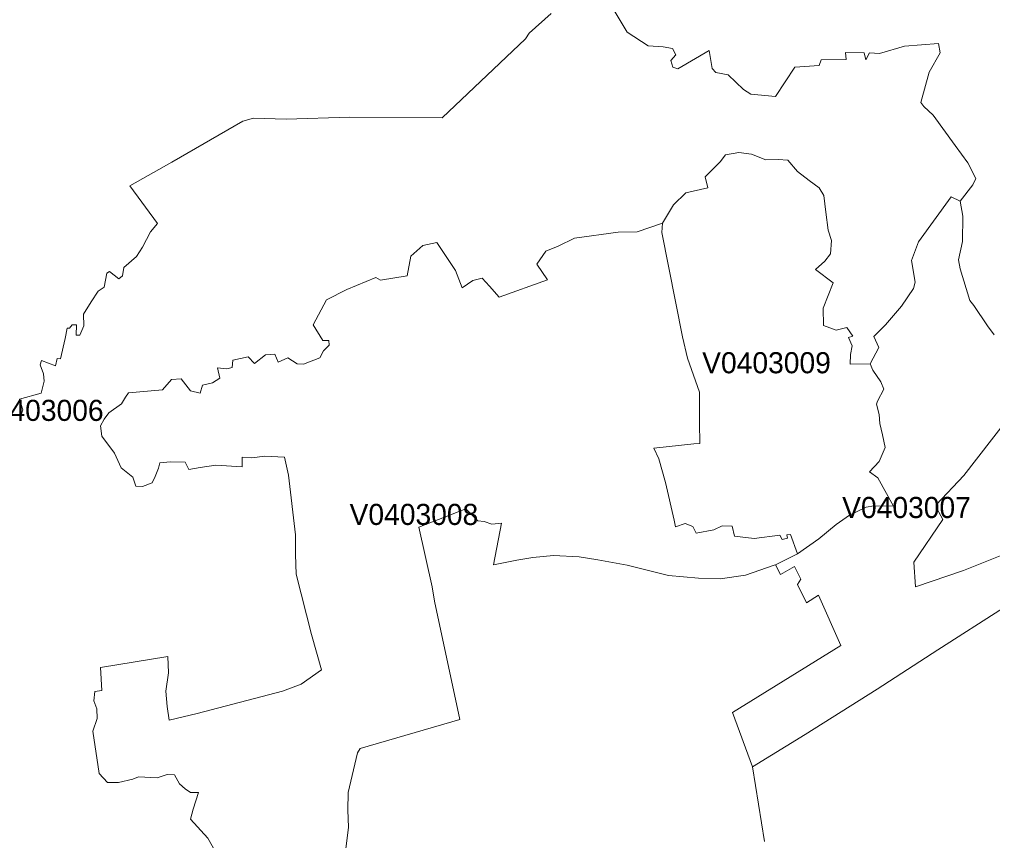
# Model space of a CAD drawing. Extents: x 369010 to 735936, y 6377141 to 6616555.
# Drawn here: x 425415 to 430026, y 6480546 to 6484437 of the extents above; entities that cross this region are included whole.
import ezdxf
from ezdxf.enums import TextEntityAlignment as Align

# ---------------------------------------------------------------- set-up
doc = ezdxf.new("R2010")
doc.units = 0
doc.header["$LTSCALE"] = 40
doc.layers.add('3', color=7, linetype='Continuous', lineweight=13)
doc.layers.add('4', color=7, linetype='Continuous')

msp = doc.modelspace()

# ---------------------------------------------------------------- linework, layer by layer
at = {"layer": '3'}
for points in [[(429443.49, 6484278.68), (429425.29, 6484245.58), (429418.01, 6484278.18), (429329.96, 6484280.83), (429331.94, 6484247.56), (429214.44, 6484245.41), (429204.67, 6484219.26), (429088.82, 6484211.65), (428997.96, 6484072.13), (428880.62, 6484083.22), (428846.19, 6484105.23), (428773.2, 6484174.41), (428715.44, 6484185.83), (428697.07, 6484205.36), (428684, 6484290.76), (428534.38, 6484203.54), (428511.54, 6484210.82), (428501.78, 6484242.76), (428525.28, 6484270.07), (428510.22, 6484299.53), (428464.7, 6484307.81), (428394.86, 6484312.27), (428294.57, 6484376.99), (428143.96, 6484628.88)], [(428143.96, 6484628.88), (428294.57, 6484376.99), (428394.86, 6484312.27), (428464.7, 6484307.81), (428510.22, 6484299.53), (428525.28, 6484270.07), (428501.78, 6484242.76), (428511.54, 6484210.82), (428534.38, 6484203.54), (428684, 6484290.76), (428697.07, 6484205.36), (428715.44, 6484185.83), (428773.2, 6484174.41), (428846.19, 6484105.23), (428880.62, 6484083.22), (428997.96, 6484072.13), (429088.82, 6484211.65), (429204.67, 6484219.26), (429214.44, 6484245.41), (429331.94, 6484247.56), (429329.96, 6484280.83), (429418.01, 6484278.18), (429425.29, 6484245.58), (429443.49, 6484278.68), (429489.84, 6484276.03), (429608.5, 6484310.12), (429769.87, 6484323.69), (429777.81, 6484278.18), (429726.18, 6484187.48), (429686.12, 6484044.32), (429699.69, 6484024.3), (429744.05, 6483983.25), (429849.14, 6483839.1), (429908.23, 6483757.34), (429947.29, 6483683.52), (429931.9, 6483652.91), (429871.98, 6483576.61), (429884.73, 6483505.44), (429884.07, 6483384.79), (429864.87, 6483297.73), (429871.98, 6483255.2), (429918.33, 6483105.75), (429937.86, 6483081.09), (430002.4, 6482984.6), (430034.18, 6482942.56)], [(427935.26, 6484465.37), (427830.66, 6484371.69), (427813.78, 6484344.88), (427418.72, 6483970.67), (426981.46, 6483974.15), (426679.41, 6483965.05), (426524, 6483969.68), (426474.35, 6483955.28), (426137.06, 6483760.81), (425937.62, 6483647.94), (426069.2, 6483470.52), (426035.93, 6483430.63), (425998.69, 6483358.14), (425969.23, 6483314.45), (425909.82, 6483261.49), (425903.36, 6483221.6), (425885.66, 6483207.2), (425842.62, 6483243.28), (425829.55, 6483234.18), (425817.14, 6483168.81), (425787.84, 6483149.28), (425754.58, 6483098.96), (425719.16, 6483040.38), (425721.14, 6482985.59), (425700.95, 6482941.24), (425684.57, 6482941.24), (425685.23, 6482989.57), (425665.7, 6482989.57), (425653.29, 6482974.51), (425640.87, 6482974.51), (425631.44, 6482924.85), (425609.1, 6482828.2), (425593.54, 6482829.52), (425586.92, 6482794.93), (425519.73, 6482821.08), (425512.94, 6482800.06), (425529.16, 6482757.03), (425532.47, 6482722.44), (425518.07, 6482666.34), (425415.79, 6482638.04), (425431.51, 6482587.72), (425422.41, 6482558.92), (425392.95, 6482561.57)], [(425685.23, 6482989.57), (425684.57, 6482941.24), (425700.95, 6482941.24), (425721.14, 6482985.59), (425719.16, 6483040.38), (425754.58, 6483098.96), (425787.84, 6483149.28), (425817.14, 6483168.81), (425829.55, 6483234.18), (425842.62, 6483243.28), (425885.66, 6483207.2), (425903.36, 6483221.6), (425909.82, 6483261.49), (425969.23, 6483314.45), (425998.69, 6483358.14), (426035.93, 6483430.63), (426069.2, 6483470.52), (425937.62, 6483647.94), (426137.06, 6483760.81), (426474.35, 6483955.28), (426524, 6483969.68), (426679.41, 6483965.05), (426981.46, 6483974.15), (427418.72, 6483970.67), (427813.78, 6484344.88), (427830.66, 6484371.69), (427935.26, 6484465.37)], [(426226.43, 6482677.26), (426271.28, 6482666.01), (426282.37, 6482704.57), (426330.7, 6482715.66), (426364.13, 6482736.68), (426354.36, 6482786.16), (426397.72, 6482781.03), (426423.21, 6482788.31), (426425.86, 6482822.9), (426499.01, 6482837.96), (426529.8, 6482807.18), (426581.27, 6482848.06), (426625.13, 6482851.37), (426640.68, 6482812.15), (426686.53, 6482833.83), (426730.88, 6482804.37), (426761.34, 6482803.87), (426838.46, 6482832.67), (426856.67, 6482867.26), (426882.15, 6482892.75), (426880.83, 6482914.92), (426852.2, 6482914.92), (426806.85, 6482989.57), (426870.24, 6483108.89), (426966.23, 6483157.22), (427103.27, 6483214.49), (427125.45, 6483201.41), (427252.55, 6483221.77), (427270.26, 6483315.11), (427326.53, 6483366.25), (427392.4, 6483379.99), (427481.94, 6483247.26), (427513.22, 6483164.5), (427563.53, 6483200.25), (427607.39, 6483211.18), (427641.98, 6483173.28), (427687.66, 6483121.14), (427917.05, 6483202.9), (427867.4, 6483277.87), (427908.94, 6483338.28), (427968.36, 6483362.94), (428045.81, 6483401.34), (428251.37, 6483429.31), (428341.4, 6483429.97), (428461.89, 6483471.02), (428514.69, 6483558.57), (428571.95, 6483616.16), (428676.38, 6483638.34), (428664.63, 6483691.8), (428735.8, 6483762.8), (428759.96, 6483795.4), (428824.51, 6483806.49), (428883.93, 6483798.72), (428952.44, 6483771.41), (429010.54, 6483772.73), (429056.71, 6483770.08), (429101.07, 6483716.63), (429156.51, 6483673.59), (429204.01, 6483639.83), (429226.19, 6483603.25), (429235.46, 6483524.31), (429246.71, 6483438.08), (429262.27, 6483389.09), (429258.3, 6483326.04), (429231.65, 6483291.45), (429186.63, 6483251.72), (429271.04, 6483188.67), (429224.04, 6483069.34), (429225.03, 6482987.25), (429284.94, 6482963.75), (429335.09, 6482976.66), (429364.55, 6482935.61), (429342.87, 6482930.48), (429360.91, 6482890.76), (429353.63, 6482849.05), (429350.98, 6482803.37), (429446.47, 6482805.69), (429487.52, 6482881.99), (429464.02, 6482934.12), (429518.8, 6482989.57), (429594.27, 6483077.95), (429651.7, 6483162.02), (429659.48, 6483192.64), (429641.27, 6483294.42), (429675.2, 6483383.8), (429829.45, 6483596.3), (429871.98, 6483576.61), (429931.9, 6483652.91), (429947.29, 6483683.52), (429908.23, 6483757.34), (429849.14, 6483839.1), (429744.05, 6483983.25), (429699.69, 6484024.3), (429686.12, 6484044.32), (429726.18, 6484187.48), (429777.81, 6484278.18), (429769.87, 6484323.69), (429608.5, 6484310.12), (429489.84, 6484276.03), (429443.49, 6484278.68)], [(430034.18, 6482942.56), (430002.4, 6482984.6), (429937.86, 6483081.09), (429918.33, 6483105.75), (429871.98, 6483255.2), (429864.87, 6483297.73), (429884.07, 6483384.79), (429884.73, 6483505.44), (429871.98, 6483576.61), (429829.45, 6483596.3), (429675.2, 6483383.8), (429641.27, 6483294.42), (429659.48, 6483192.64), (429651.7, 6483162.02), (429594.27, 6483077.95), (429518.8, 6482989.57), (429464.02, 6482934.12), (429487.52, 6482881.99), (429446.47, 6482805.69), (429458.89, 6482774.25), (429497.28, 6482720.13), (429511.02, 6482684.38), (429480.73, 6482628.44), (429476.1, 6482613.38), (429488.51, 6482565.21), (429491.16, 6482521.52), (429504.9, 6482468.06), (429517.47, 6482408.15), (429488.84, 6482341.62), (429442.5, 6482293.46), (429482.22, 6482264), (429556.2, 6482129.61), (429463.02, 6482132.09), (429427.77, 6482126.3), (429348.16, 6482087.07), (429284.94, 6482043.38), (429202.69, 6481975.52), (429102.23, 6481904.19), (428997.63, 6481853.05), (429021.29, 6481805.72), (429087.16, 6481844.94), (429117.78, 6481784.53), (429101.56, 6481758.55), (429144.59, 6481672.49), (429201.36, 6481708.9), (429307.78, 6481469.74), (428793.56, 6481152.64), (428888.73, 6480894.78), (429137.81, 6481048.54), (429478.91, 6481262.37), (429767.05, 6481449.55), (430389.52, 6481847.92)], [(428461.89, 6483471.02), (428341.4, 6483429.97), (428251.37, 6483429.31), (428045.81, 6483401.34), (427968.36, 6483362.94), (427908.94, 6483338.28), (427867.4, 6483277.87), (427917.05, 6483202.9), (427687.66, 6483121.14), (427641.98, 6483173.28), (427607.39, 6483211.18), (427563.53, 6483200.25), (427513.22, 6483164.5), (427481.94, 6483247.26), (427392.4, 6483379.99), (427326.53, 6483366.25), (427270.26, 6483315.11), (427252.55, 6483221.77), (427125.45, 6483201.41), (427103.27, 6483214.49), (426966.23, 6483157.22), (426870.24, 6483108.89), (426806.85, 6482989.57), (426852.2, 6482914.92), (426880.83, 6482914.92), (426882.15, 6482892.75), (426856.67, 6482867.26), (426838.46, 6482832.67), (426761.34, 6482803.87), (426730.88, 6482804.37), (426686.53, 6482833.83), (426640.68, 6482812.15), (426625.13, 6482851.37), (426581.27, 6482848.06), (426529.8, 6482807.18), (426499.01, 6482837.96), (426425.86, 6482822.9), (426423.21, 6482788.31), (426397.72, 6482781.03), (426354.36, 6482786.16), (426364.13, 6482736.68), (426330.7, 6482715.66), (426282.37, 6482704.57), (426271.28, 6482666.01), (426226.43, 6482677.26), (426182.07, 6482733.37), (426135.57, 6482730.06), (426093.2, 6482681.73), (425932.66, 6482667.16), (425917.1, 6482647.14), (425898.73, 6482615.2), (425839.31, 6482572), (425816.47, 6482542.71), (425799.92, 6482511.26), (425805.05, 6482461.61), (425865.79, 6482381.34), (425897.9, 6482312.49), (425952.02, 6482268.13), (425967.08, 6482225.77), (425998.03, 6482224.28), (426043.88, 6482241.16), (426058.77, 6482270.62), (426073.83, 6482311), (426079.79, 6482335.16), (426130.77, 6482339.8), (426200.44, 6482339.3), (426217.33, 6482303.39), (426272.27, 6482313.15), (426345.92, 6482324.07), (426470.05, 6482316.79), (426470.88, 6482362.64), (426515.89, 6482358.83), (426577.96, 6482366.61), (426671.47, 6482363.3), (426689.67, 6482276.57), (426723.11, 6481994.72), (426723.77, 6481901.21), (426726.91, 6481808.53), (426799.24, 6481522.87), (426846.41, 6481354.55), (426749.59, 6481286.2), (426661.37, 6481253.43), (426257.54, 6481147.84), (426124.15, 6481115.4), (426115.54, 6481181.43), (426109.25, 6481254.09), (426122.16, 6481340.15), (426118.52, 6481417.11), (425799.76, 6481365.81), (425805.05, 6481256.08), (425772.28, 6481252.11), (425768.31, 6481208.08), (425782.05, 6481170.18), (425783.37, 6481123.84), (425763.84, 6481064.42), (425792.48, 6480863.34), (425832.2, 6480820.31), (425884, 6480819.97), (425951.86, 6480836.36), (425980.16, 6480847.45)], [(426957.79, 6480468.94), (426974.67, 6480608.96), (426971.69, 6480689.56), (426972.35, 6480773.63), (427016.54, 6480960.98), (427030.28, 6480981.84), (427502.13, 6481119.04), (427381.31, 6481679.93), (427371.38, 6481747.46), (427308.16, 6482030.14), (427530.27, 6482117.86), (427587.7, 6482061.09), (427617.16, 6482057.28), (427653.4, 6482045.53), (427699.74, 6482049.5), (427661.84, 6481852.72), (427771.41, 6481874.23), (427847.37, 6481886.65), (427945.35, 6481896.25), (428067.99, 6481889.63), (428156.2, 6481875.89), (428294.4, 6481850.07), (428491.35, 6481802.41), (428633.52, 6481789.83), (428735.3, 6481786.52), (428855.13, 6481802.74), (428991.34, 6481850.07), (428997.63, 6481853.05), (429102.23, 6481904.19), (429068.3, 6481995.38), (429051.42, 6481994.72), (429053.9, 6481979.16), (429028.58, 6481972.05), (429017.49, 6481992.24), (428896.67, 6481977.67), (428803.99, 6481988.1), (428792.24, 6482035.1), (428744.9, 6482037.09), (428705.18, 6482018.89), (428621.6, 6482002.17), (428605.22, 6482034.11), (428569.96, 6482047.85), (428523.29, 6482033.12), (428517.33, 6482063.74), (428477.12, 6482242.15), (428444.51, 6482354.2), (428421.01, 6482405.83), (428610.18, 6482426.19), (428638.81, 6482426.85), (428637.32, 6482524.83), (428637.99, 6482670.14), (428580.06, 6482831.84), (428556.56, 6482933.63), (428459.24, 6483427.32), (428461.89, 6483471.02)], [(425392.95, 6482561.57), (425422.41, 6482558.92), (425431.51, 6482587.72), (425415.79, 6482638.04), (425518.07, 6482666.34), (425532.47, 6482722.44), (425529.16, 6482757.03), (425512.94, 6482800.06), (425519.73, 6482821.08), (425586.92, 6482794.93), (425593.54, 6482829.52), (425609.1, 6482828.2), (425631.44, 6482924.85), (425640.87, 6482974.51), (425653.29, 6482974.51), (425665.7, 6482989.57), (425685.23, 6482989.57)], [(426343.27, 6480494.92), (426308.68, 6480556.33), (426226.1, 6480647.52), (426237.85, 6480694.52), (426263.67, 6480773.3), (426225.1, 6480773.3), (426199.78, 6480790.85), (426172.97, 6480815.01), (426150.13, 6480856.88), (426115.37, 6480859.2), (426067.71, 6480842.32), (425980.16, 6480847.45), (425951.86, 6480836.36), (425884, 6480819.97), (425832.2, 6480820.31), (425792.48, 6480863.34), (425763.84, 6481064.42), (425783.37, 6481123.84), (425782.05, 6481170.18), (425768.31, 6481208.08), (425772.28, 6481252.11), (425805.05, 6481256.08), (425799.76, 6481365.81), (426118.52, 6481417.11), (426122.16, 6481340.15), (426109.25, 6481254.09), (426115.54, 6481181.43), (426124.15, 6481115.4), (426257.54, 6481147.84), (426661.37, 6481253.43), (426749.59, 6481286.2), (426846.41, 6481354.55), (426799.24, 6481522.87), (426726.91, 6481808.53), (426723.77, 6481901.21), (426723.11, 6481994.72), (426689.67, 6482276.57), (426671.47, 6482363.3), (426577.96, 6482366.61), (426515.89, 6482358.83), (426470.88, 6482362.64), (426470.05, 6482316.79), (426345.92, 6482324.07), (426272.27, 6482313.15), (426217.33, 6482303.39), (426200.44, 6482339.3), (426130.77, 6482339.8), (426079.79, 6482335.16), (426073.83, 6482311), (426058.77, 6482270.62), (426043.88, 6482241.16), (425998.03, 6482224.28), (425967.08, 6482225.77), (425952.02, 6482268.13), (425897.9, 6482312.49), (425865.79, 6482381.34), (425805.05, 6482461.61), (425799.92, 6482511.26), (425816.47, 6482542.71), (425839.31, 6482572), (425898.73, 6482615.2), (425917.1, 6482647.14), (425932.66, 6482667.16), (426093.2, 6482681.73), (426135.57, 6482730.06), (426182.07, 6482733.37), (426226.43, 6482677.26)], [(430092.77, 6482535.75), (429889.53, 6482276.08), (429758.61, 6482135.9), (429761.92, 6482118.85), (429789.89, 6482067.38), (429652.36, 6481864.47), (429661.63, 6481748.29), (429888.37, 6481825.91), (430084.99, 6481904.85)], [(430084.99, 6481904.85), (429888.37, 6481825.91), (429661.63, 6481748.29), (429652.36, 6481864.47), (429789.89, 6482067.38), (429761.92, 6482118.85), (429758.61, 6482135.9), (429889.53, 6482276.08), (430092.77, 6482535.75)], [(427945.35, 6481896.25), (427847.37, 6481886.65), (427771.41, 6481874.23), (427661.84, 6481852.72), (427699.74, 6482049.5), (427653.4, 6482045.53), (427617.16, 6482057.28), (427587.7, 6482061.09), (427530.27, 6482117.86), (427308.16, 6482030.14), (427371.38, 6481747.46), (427381.31, 6481679.93), (427502.13, 6481119.04), (427030.28, 6480981.84), (427016.54, 6480960.98), (426972.35, 6480773.63), (426971.69, 6480689.56), (426974.67, 6480608.96), (426957.79, 6480468.94)], [(428945.33, 6480540.27), (428888.73, 6480894.78), (428793.56, 6481152.64), (429307.78, 6481469.74), (429201.36, 6481708.9), (429144.59, 6481672.49), (429101.56, 6481758.55), (429117.78, 6481784.53), (429087.16, 6481844.94), (429021.29, 6481805.72), (428997.63, 6481853.05), (428991.34, 6481850.07), (428855.13, 6481802.74), (428735.3, 6481786.52), (428633.52, 6481789.83), (428491.35, 6481802.41), (428294.4, 6481850.07), (428156.2, 6481875.89), (428067.99, 6481889.63), (427945.35, 6481896.25)], [(433652.59, 6481829.22), (433088.22, 6481856.03), (432584.6, 6481905.02), (432564.9, 6481819.45), (432271.46, 6481548.52), (432030.65, 6481337.51), (431747.97, 6481115.07), (431433.85, 6480866.81), (431146.86, 6480633.29), (430755.94, 6480931.03), (430622.21, 6481241.18), (430389.52, 6481847.92), (429767.05, 6481449.55), (429478.91, 6481262.37), (429137.81, 6481048.54), (428888.73, 6480894.78), (428945.33, 6480540.27)], [(425980.16, 6480847.45), (426067.71, 6480842.32), (426115.37, 6480859.2), (426150.13, 6480856.88), (426172.97, 6480815.01), (426199.78, 6480790.85), (426225.1, 6480773.3), (426263.67, 6480773.3), (426237.85, 6480694.52), (426226.1, 6480647.52), (426308.68, 6480556.33), (426343.27, 6480494.92)]]:
    msp.add_lwpolyline(points, dxfattribs=at)
msp.add_lwpolyline([(428461.89, 6483471.02), (428459.24, 6483427.32), (428556.56, 6482933.63), (428580.06, 6482831.84), (428637.99, 6482670.14), (428637.32, 6482524.83), (428638.81, 6482426.85), (428610.18, 6482426.19), (428421.01, 6482405.83), (428444.51, 6482354.2), (428477.12, 6482242.15), (428517.33, 6482063.74), (428523.29, 6482033.12), (428569.96, 6482047.85), (428605.22, 6482034.11), (428621.6, 6482002.17), (428705.18, 6482018.89), (428744.9, 6482037.09), (428792.24, 6482035.1), (428803.99, 6481988.1), (428896.67, 6481977.67), (429017.49, 6481992.24), (429028.58, 6481972.05), (429053.9, 6481979.16), (429051.42, 6481994.72), (429068.3, 6481995.38), (429102.23, 6481904.19), (429202.69, 6481975.52), (429284.94, 6482043.38), (429348.16, 6482087.07), (429427.77, 6482126.3), (429463.02, 6482132.09), (429556.2, 6482129.61), (429482.22, 6482264), (429442.5, 6482293.46), (429488.84, 6482341.62), (429517.47, 6482408.15), (429504.9, 6482468.06), (429491.16, 6482521.52), (429488.51, 6482565.21), (429476.1, 6482613.38), (429480.73, 6482628.44), (429511.02, 6482684.38), (429497.28, 6482720.13), (429458.89, 6482774.25), (429446.47, 6482805.69), (429350.98, 6482803.37), (429353.63, 6482849.05), (429360.91, 6482890.76), (429342.87, 6482930.48), (429364.55, 6482935.61), (429335.09, 6482976.66), (429284.94, 6482963.75), (429225.03, 6482987.25), (429224.04, 6483069.34), (429271.04, 6483188.67), (429186.63, 6483251.72), (429231.65, 6483291.45), (429258.3, 6483326.04), (429262.27, 6483389.09), (429246.71, 6483438.08), (429235.46, 6483524.31), (429226.19, 6483603.25), (429204.01, 6483639.83), (429156.51, 6483673.59), (429101.07, 6483716.63), (429056.71, 6483770.08), (429010.54, 6483772.73), (428952.44, 6483771.41), (428883.93, 6483798.72), (428824.51, 6483806.49), (428759.96, 6483795.4), (428735.8, 6483762.8), (428664.63, 6483691.8), (428676.38, 6483638.34), (428571.95, 6483616.16), (428514.69, 6483558.57)], close=True, dxfattribs=at)

# ---------------------------------------------------------------- texts
at = {"layer": '4'}
for s, p in [('V0403009', (428955, 6482760.19)), ('V0403006', (425509.32, 6482534.47)), ('V0403007', (429618.26, 6482074.16)), ('V0403008', (427284.35, 6482041.24))]:
    msp.add_text(s, height=100, dxfattribs=at).set_placement(p, align=Align.CENTER)

doc.saveas('drawing.dxf')
